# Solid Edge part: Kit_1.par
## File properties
Author: bmolnar
Last saved by: bmolnar
Revision: 76
Sűrűség: 0,000 kg/m^3
Pontosság: 0,990
Username: bmolnar
Dokumentum tartalom típus: 0
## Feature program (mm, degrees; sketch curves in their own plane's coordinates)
base feature "unnamed BaseFeature 1"
sketch for "Furat_1" plane through (-20.15, 0, -7.65) normal (1, 0, 0) x-axis (0, -1, 0)
  hole centre (0, -15.15) bore radius 2.067
hole "Furat_1" nominal diameter 5 finite  StartChamferOffset = 0.6 mm; StartChamferAngle = 45 deg
sketch for "Furat_2" plane through (-13, 13, 5.1) normal (0, 0, -1) x-axis (0, -1, 0)
  hole centre (0, 0) bore radius 2.067
hole "Furat_2" nominal diameter 5
sketch for "unnamed Hole 1" plane through (-13, 13, 5.1) normal (0, 0, -1) x-axis (0, -1, 0)
  hole centre (26, 0) bore radius 2.067
hole "unnamed Hole 1"
sketch for "unnamed Hole 2" plane through (-13, 13, 5.1) normal (0, 0, -1) x-axis (0, -1, 0)
  hole centre (26, -26) bore radius 2.067
hole "unnamed Hole 2"
sketch for "unnamed Hole 3" plane through (-13, 13, 5.1) normal (0, 0, -1) x-axis (0, -1, 0)
  hole centre (0, -26) bore radius 2.067
hole "unnamed Hole 3"
pattern "unnamed Pattern 1" of "Furat_2", "unnamed Hole 1", "unnamed Hole 2", "unnamed Hole 3"
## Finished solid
Body 1: solid body, 245 faces, 610 edges, 376 vertices, 3 internal voids.
  Faces by surface: plane 129, cylinder 52, swept 42, cone 16, torus 6
  Edges by curve: line 381, circle 135, spline 88, curve on surface 5, ellipse 1
Bounding box of the edges (mm; curved faces can reach further): 40.300 x 40.300 x 12.500, from (-20.15, -20.15, 0) to (20.15, 20.15, 12.5).
Cylindrical faces by radius (mm): R0.2 x18, R0.4246 x1, R0.4865 x1, R2.067 x5, R3.75 x2, R4 x4, R4.1 x12, R4.5 x1, R5.45 x2, R5.55 x2, R13.75 x4
Conical faces (half-angle, radius in mm at the cone's reference point): 0.5 deg R5 x4, 45 deg R2.317 x2, 45 deg R2.367 x2, 45 deg R2.667 x1, 45 deg R4.25 x2, 45 deg R4.65 x1, 45 deg R5.3 x2, 45 deg R5.35 x2
Toroidal faces (ring radius, tube radius in mm): R3.8 r0.2 x2, R4.4 r0.4 x2, R9.4957 r0.5 x1, R11.0043 r0.5 x1
Planar faces by outward normal: +x 5, +y 13, +z 4, -x 7, -y 16, -z 15, oblique 69
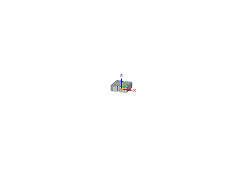
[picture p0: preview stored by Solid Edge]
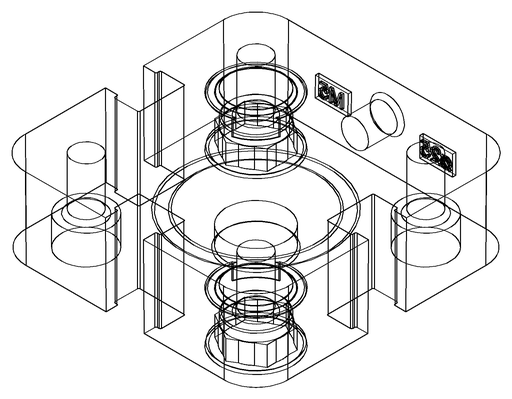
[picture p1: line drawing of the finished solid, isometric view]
